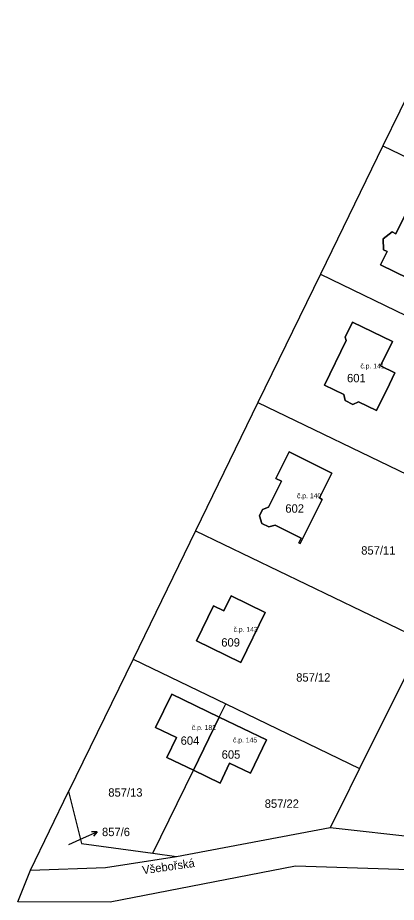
# Model space of a CAD drawing. Extents: x -887272 to -880188, y -1026687 to -1021896.
# Drawn here: x -886466.5 to -886389.5, y -1024379 to -1024199.3 of the extents above; entities that cross this region are included whole.
import ezdxf

# ---------------------------------------------------------------- set-up
doc = ezdxf.new("R2010")
doc.units = 0
for name, color, linetype in [('Definiční body', 7, 'Continuous'), ('Hranice parcel', 7, 'Continuous'), ('Parcelní čísla', 7, 'Continuous'), ('Polygon budovy', 7, 'Continuous'), ('Pop  PČ popisy', 7, 'Continuous')]:
    doc.layers.add(name, color=color, linetype=linetype)

msp = doc.modelspace()

# ---------------------------------------------------------------- linework, layer by layer
at = {"layer": 'Hranice parcel'}
for p, q in [((-886379.52, -1024199.32), (-886392.22, -1024225.37)), ((-886392.22, -1024225.37), (-886404.92, -1024251.42)), ((-886392.22, -1024225.37), (-886350.92, -1024245.18)), ((-886404.92, -1024251.42), (-886417.61, -1024277.46)), ((-886404.92, -1024251.42), (-886358, -1024274.01)), ((-886417.61, -1024277.46), (-886430.31, -1024303.51)), ((-886417.61, -1024277.46), (-886370.98, -1024299.95)), ((-886430.31, -1024303.51), (-886443.01, -1024329.56)), ((-886430.31, -1024303.51), (-886383.96, -1024325.88)), ((-886443.01, -1024329.56), (-886456.12, -1024356.46)), ((-886443.01, -1024329.56), (-886424.18, -1024338.65)), ((-886396.94, -1024351.81), (-886386.87, -1024331.69)), ((-886425.5, -1024341.35), (-886424.18, -1024338.65)), ((-886424.18, -1024338.65), (-886396.94, -1024351.81)), ((-886430.75, -1024352.13), (-886425.5, -1024341.35)), ((-886438.98, -1024368.98), (-886430.75, -1024352.13)), ((-886463.9, -1024372.42), (-886456.12, -1024356.46)), ((-886456.12, -1024356.46), (-886453.52, -1024367.02)), ((-886434.16, -1024369.63), (-886402.91, -1024363.76)), ((-886453.52, -1024367.02), (-886438.98, -1024368.98)), ((-886438.98, -1024368.98), (-886434.16, -1024369.63)), ((-886466.48, -1024378.88), (-886463.9, -1024372.42)), ((-886447.7, -1024378.96), (-886466.48, -1024378.88))]:
    msp.add_line(p, q, dxfattribs=at)
for points in [[(-886381.46, -1024255.02), (-886392.68, -1024249.51), (-886391.36, -1024246.82), (-886392.1, -1024246.44), (-886392.15, -1024244.24), (-886390.31, -1024242.82), (-886389.57, -1024243.18), (-886385.19, -1024234.27)], [(-886398.36, -1024261.13), (-886390.29, -1024265.08), (-886392.71, -1024270.03), (-886389.79, -1024271.46), (-886390.88, -1024273.71), (-886393.51, -1024279.08), (-886397.15, -1024277.31), (-886398.34, -1024277.84), (-886399.87, -1024277.08), (-886400.15, -1024275.84), (-886404.06, -1024273.92), (-886399.66, -1024264.9), (-886399.88, -1024264.22), (-886398.36, -1024261.13)], [(-886411.26, -1024287.46), (-886402.61, -1024291.81), (-886405.13, -1024296.84), (-886404.54, -1024297.14), (-886409.05, -1024306.11), (-886409.29, -1024305.98), (-886408.84, -1024305.04), (-886414.14, -1024302.34), (-886415.43, -1024302.69), (-886416.81, -1024302.01), (-886417.31, -1024300.51), (-886416.7, -1024299.2), (-886415.46, -1024298.71), (-886412.86, -1024293.46), (-886413.96, -1024292.89), (-886411.26, -1024287.46)], [(-886426.65, -1024318.76), (-886424.56, -1024319.78), (-886423.07, -1024316.73), (-886416.12, -1024320.12), (-886421.07, -1024330.28), (-886430.11, -1024325.87), (-886426.65, -1024318.76)], [(-886430.75, -1024352.13), (-886436.15, -1024349.53), (-886434.18, -1024345.48), (-886438.42, -1024343.43), (-886435.16, -1024336.68), (-886425.5, -1024341.35)], [(-886425.5, -1024341.35), (-886415.88, -1024345.99), (-886419.14, -1024352.73), (-886423.37, -1024350.69), (-886425.32, -1024354.75), (-886430.75, -1024352.13)], [(-886396.94, -1024351.81), (-886401, -1024359.93), (-886402.91, -1024363.76)], [(-886402.91, -1024363.76), (-886384.69, -1024365.77), (-886366.93, -1024376.02)], [(-886463.9, -1024372.42), (-886448.62, -1024371.9), (-886434.16, -1024369.63)], [(-886384.8, -1024372.44), (-886410, -1024371.64), (-886447.7, -1024378.96)]]:
    msp.add_lwpolyline(points, dxfattribs=at)
at = {"layer": 'Polygon budovy'}
msp.add_lwpolyline([(-886385.19, -1024234.27), (-886389.57, -1024243.18), (-886390.31, -1024242.82), (-886392.15, -1024244.24), (-886392.1, -1024246.44), (-886391.36, -1024246.82), (-886392.68, -1024249.51), (-886381.46, -1024255.02)], dxfattribs=at)
for points in [[(-886393.51, -1024279.08), (-886390.88, -1024273.71), (-886389.79, -1024271.46), (-886392.71, -1024270.03), (-886390.29, -1024265.08), (-886398.36, -1024261.13), (-886399.88, -1024264.22), (-886399.66, -1024264.9), (-886404.06, -1024273.92), (-886400.15, -1024275.84), (-886399.87, -1024277.08), (-886398.34, -1024277.84), (-886397.15, -1024277.31)], [(-886411.26, -1024287.46), (-886413.96, -1024292.89), (-886412.86, -1024293.46), (-886415.46, -1024298.71), (-886416.7, -1024299.2), (-886417.31, -1024300.51), (-886416.81, -1024302.01), (-886415.43, -1024302.69), (-886414.14, -1024302.34), (-886408.84, -1024305.04), (-886409.29, -1024305.98), (-886409.05, -1024306.11), (-886404.54, -1024297.14), (-886405.13, -1024296.84), (-886402.61, -1024291.81)], [(-886421.07, -1024330.28), (-886416.12, -1024320.12), (-886423.07, -1024316.73), (-886424.56, -1024319.78), (-886426.65, -1024318.76), (-886430.11, -1024325.87)], [(-886435.16, -1024336.68), (-886438.42, -1024343.43), (-886434.18, -1024345.48), (-886436.15, -1024349.53), (-886430.75, -1024352.13), (-886425.5, -1024341.35)], [(-886430.75, -1024352.13), (-886425.32, -1024354.75), (-886423.37, -1024350.69), (-886419.14, -1024352.73), (-886415.88, -1024345.99), (-886425.5, -1024341.35)]]:
    msp.add_lwpolyline(points, close=True, dxfattribs=at)
at = {"layer": 'Pop  PČ popisy'}
for p, q in [((-886453.07, -1024365.89), (-886450.33, -1024364.67)), ((-886450.33, -1024364.67), (-886451.45, -1024364.62)), ((-886450.33, -1024364.67), (-886451.04, -1024365.53)), ((-886456.09, -1024367.24), (-886453.07, -1024365.89))]:
    msp.add_line(p, q, dxfattribs=at)

# ---------------------------------------------------------------- texts
at = {"layer": 'Definiční body'}
for s, p in [('č.p. 141', (-886396.78, -1024270.55)), ('č.p. 140', (-886409.67, -1024296.91)), ('č.p. 143', (-886422.58, -1024324.03)), ('č.p. 182', (-886431.07, -1024343.97)), ('č.p. 145', (-886422.69, -1024346.5))]:
    msp.add_text(s, height=1, dxfattribs=at).set_placement(p)
at = {"layer": 'Parcelní čísla'}
for s, p in [('601', (-886399.5, -1024273.36)), ('602', (-886412.05, -1024299.84)), ('857/11', (-886396.62, -1024308.35)), ('609', (-886425.08, -1024327.03)), ('857/12', (-886409.84, -1024334.14)), ('604', (-886433.34, -1024346.97)), ('605', (-886425, -1024349.8)), ('857/13', (-886448.05, -1024357.5)), ('857/22', (-886416.24, -1024359.77)), ('857/6', (-886449.33, -1024365.52))]:
    msp.add_text(s, height=1.7, dxfattribs=at).set_placement(p)
at = {"layer": 'Pop  PČ popisy'}
msp.add_text('Všebořská', height=1.7, rotation=8, dxfattribs=at).set_placement((-886441.02, -1024373.28))

doc.saveas('drawing.dxf')
